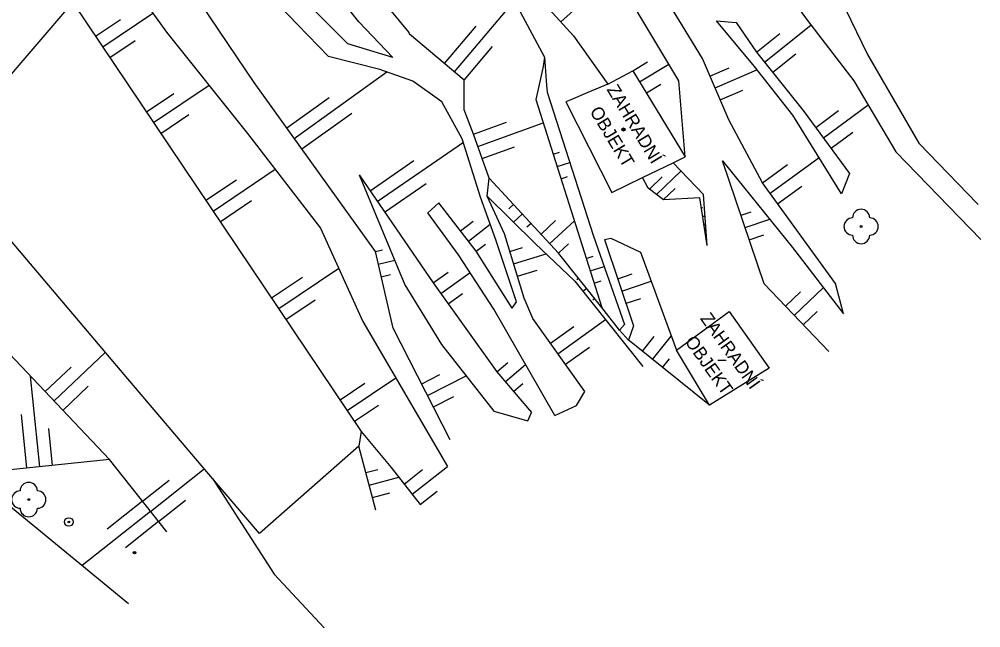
# Model space of a CAD drawing. Extents: x -639440 to -639026, y -1138850 to -1138262.
# Drawn here: x -639133 to -639077.2, y -1138746.6 to -1138711.3 of the extents above; entities that cross this region are included whole.
import ezdxf

# ---------------------------------------------------------------- set-up
doc = ezdxf.new("R2010")
doc.units = 0
for name, color, linetype in [('Vrstva 14', 7, 'Continuous'), ('Vrstva 15', 7, 'Continuous'), ('Vrstva 20', 7, 'Continuous'), ('Vrstva 22', 7, 'Continuous'), ('Vrstva 25', 7, 'Continuous'), ('Vrstva 39', 7, 'Continuous'), ('Vrstva 41', 7, 'Continuous'), ('Vrstva 5', 7, 'Continuous'), ('Vrstva 6', 7, 'Continuous'), ('Vrstva 7', 7, 'Continuous')]:
    doc.layers.add(name, color=color, linetype=linetype)

msp = doc.modelspace()

# ---------------------------------------------------------------- linework, layer by layer
at = {"layer": 'Vrstva 14'}
for p, q in [((-639110.36, -1138712.02), (-639116.41, -1138704.78)), ((-639090.86, -1138706.35), (-639087.24, -1138711.33)), ((-639113.3, -1138711.41), (-639116.94, -1138706.79)), ((-639127.37, -1138707.94), (-639124.46, -1138712)), ((-639093.34, -1138713.54), (-639096.39, -1138708.53)), ((-639103.74, -1138709), (-639100.82, -1138712.23)), ((-639094.71, -1138714.83), (-639098.05, -1138709.26)), ((-639116.85, -1138711.56), (-639118.69, -1138709.65)), ((-639104.71, -1138709.34), (-639102.5, -1138713.46)), ((-639119.36, -1138714.93), (-639122.47, -1138710.35)), ((-639113.92, -1138712.69), (-639116.43, -1138710.19)), ((-639111.32, -1138713.47), (-639113.3, -1138711.41)), ((-639092.51, -1138711.36), (-639091.38, -1138711.44)), ((-639090.32, -1138714.01), (-639092.51, -1138711.36)), ((-639091.38, -1138711.44), (-639090.19, -1138713.16)), ((-639087.24, -1138711.33), (-639084.54, -1138714.83)), ((-639124.46, -1138712), (-639119.75, -1138717.9)), ((-639115.05, -1138713.43), (-639116.85, -1138711.56)), ((-639110.35, -1138712.12), (-639110.36, -1138712.02)), ((-639107.17, -1138714.8), (-639110.35, -1138712.12)), ((-639100.82, -1138712.23), (-639098.83, -1138715.02)), ((-639111.32, -1138713.47), (-639113.92, -1138712.69)), ((-639090.19, -1138713.16), (-639087.48, -1138716.55)), ((-639112.08, -1138714.17), (-639115.05, -1138713.43)), ((-639102.5, -1138713.46), (-639102.59, -1138714.01)), ((-639102.5, -1138713.46), (-639102.4, -1138715.08)), ((-639091.8, -1138717.1), (-639093.34, -1138713.54)), ((-639110.15, -1138714.86), (-639112.08, -1138714.17)), ((-639102.59, -1138714.01), (-639103.01, -1138715.91)), ((-639088.09, -1138716.82), (-639090.32, -1138714.01)), ((-639108.47, -1138716.05), (-639110.15, -1138714.86)), ((-639107.17, -1138716.52), (-639107.17, -1138714.8)), ((-639094.34, -1138719.25), (-639094.71, -1138714.83)), ((-639084.54, -1138714.83), (-639082.11, -1138718.95)), ((-639112.33, -1138724.74), (-639119.36, -1138714.93)), ((-639102.4, -1138715.08), (-639102.35, -1138715.49)), ((-639103.01, -1138715.91), (-639099.17, -1138728)), ((-639102.35, -1138715.49), (-639099.66, -1138723.85)), ((-639107.28, -1138718.2), (-639108.47, -1138716.05)), ((-639106.64, -1138717.93), (-639107.17, -1138716.52)), ((-639087.48, -1138716.55), (-639084.79, -1138720.21)), ((-639089.85, -1138720.75), (-639091.8, -1138717.1)), ((-639085.25, -1138721.39), (-639088.09, -1138716.82)), ((-639119.75, -1138717.9), (-639115.52, -1138723.39)), ((-639106.23, -1138721.58), (-639107.28, -1138718.2)), ((-639105.72, -1138720.48), (-639106.64, -1138717.93)), ((-639082.11, -1138718.95), (-639077.17, -1138724.05)), ((-639093.28, -1138721.44), (-639095.04, -1138719.59)), ((-639089.75, -1138726.62), (-639092.16, -1138719.47)), ((-639092.16, -1138719.47), (-639088.11, -1138724.5)), ((-639113.28, -1138720.28), (-639108.97, -1138726.56)), ((-639113.28, -1138720.28), (-639110.61, -1138726.68)), ((-639096.48, -1138721.06), (-639096.81, -1138720.44)), ((-639084.79, -1138720.21), (-639085.25, -1138721.39)), ((-639105.84, -1138721.53), (-639105.72, -1138720.48)), ((-639101.69, -1138724.83), (-639105.72, -1138720.48)), ((-639085.6, -1138726.6), (-639089.85, -1138720.75)), ((-639105.33, -1138724.06), (-639106.23, -1138721.58)), ((-639105.84, -1138721.53), (-639103.04, -1138724.28)), ((-639104.84, -1138723.72), (-639105.84, -1138721.53)), ((-639095.59, -1138721.75), (-639096.48, -1138721.06)), ((-639093.06, -1138724.39), (-639093.28, -1138721.44)), ((-639109.28, -1138722.5), (-639108.65, -1138721.92)), ((-639106.47, -1138724.73), (-639108.65, -1138721.92)), ((-639093.49, -1138721.62), (-639095.59, -1138721.75)), ((-639093.06, -1138724.39), (-639093.49, -1138721.62)), ((-639107.5, -1138724.93), (-639109.28, -1138722.5)), ((-639115.52, -1138723.39), (-639113.05, -1138728.8)), ((-639103.69, -1138727.44), (-639104.84, -1138723.72)), ((-639104.13, -1138727.67), (-639105.33, -1138724.06)), ((-639103.04, -1138724.28), (-639100.74, -1138726.47)), ((-639099.66, -1138723.85), (-639097.87, -1138728.98)), ((-639099.02, -1138724.05), (-639098.66, -1138723.96)), ((-639099.02, -1138724.05), (-639097.33, -1138729.05)), ((-639098.66, -1138723.96), (-639096.94, -1138724.77)), ((-639111.29, -1138729.19), (-639112.33, -1138724.74)), ((-639105.45, -1138728.08), (-639107.5, -1138724.93)), ((-639104.38, -1138728.03), (-639106.47, -1138724.73)), ((-639099.17, -1138728), (-639101.69, -1138724.83)), ((-639096.94, -1138724.77), (-639094.85, -1138730.47)), ((-639088.11, -1138724.5), (-639085.14, -1138728.35)), ((-639108.97, -1138726.56), (-639105.28, -1138731.73)), ((-639100.74, -1138726.47), (-639096.79, -1138731.41)), ((-639086, -1138730.55), (-639089.75, -1138726.62)), ((-639085.14, -1138728.35), (-639085.6, -1138726.6)), ((-639110.61, -1138726.68), (-639108.48, -1138730.13)), ((-639104.38, -1138728.03), (-639104.13, -1138727.67)), ((-639103.19, -1138728.63), (-639103.69, -1138727.44)), ((-639101.91, -1138734.26), (-639105.45, -1138728.08)), ((-639098.16, -1138729.3), (-639099.17, -1138728)), ((-639113.05, -1138728.8), (-639108.139, -1138737.215)), ((-639100.16, -1138732.87), (-639103.19, -1138728.63)), ((-639107.98, -1138735.67), (-639111.29, -1138729.19)), ((-639097.87, -1138728.98), (-639098.16, -1138729.3)), ((-639097.62, -1138729.89), (-639098.16, -1138729.3)), ((-639097.33, -1138729.05), (-639097.62, -1138729.89)), ((-639134.45, -1138729.77), (-639127.78, -1138736.82)), ((-639097.29, -1138730.16), (-639097.62, -1138729.89)), ((-639108.48, -1138730.13), (-639105.45, -1138734.01)), ((-639092.92, -1138733.66), (-639097.29, -1138730.16)), ((-639105.28, -1138731.73), (-639103.27, -1138734.08)), ((-639100.64, -1138733.68), (-639100.16, -1138732.87)), ((-639101.91, -1138734.26), (-639100.64, -1138733.68)), ((-639105.45, -1138734.01), (-639103.47, -1138734.57)), ((-639103.47, -1138734.57), (-639103.27, -1138734.08)), ((-639112.3, -1138739.75), (-639113.3, -1138736.03)), ((-639127.78, -1138736.82), (-639135.85, -1138737.64)), ((-639124.44, -1138741.02), (-639127.78, -1138736.82)), ((-639135.85, -1138737.64), (-639126.67, -1138745.17)), ((-639121.79, -1138737.92), (-639118.2, -1138743.47)), ((-639118.2, -1138743.47), (-639115.31, -1138746.58))]:
    msp.add_line(p, q, dxfattribs=at)
at = {"layer": 'Vrstva 15'}
for p, q in [((-639107.743, -1138714.317), (-639104.259, -1138710.182)), ((-639101.568, -1138711.403), (-639100.109, -1138710.084)), ((-639128.166, -1138712.866), (-639125.247, -1138710.902)), ((-639128.585, -1138712.244), (-639127.135, -1138711.268)), ((-639108.317, -1138713.833), (-639106.479, -1138711.652)), ((-639090.19, -1138713.16), (-639088.836, -1138712.078)), ((-639089.721, -1138713.746), (-639087.034, -1138711.598)), ((-639127.748, -1138713.488), (-639126.279, -1138712.5)), ((-639107.17, -1138714.8), (-639105.524, -1138712.846)), ((-639097.37, -1138714.25), (-639096.522, -1138713.736)), ((-639089.253, -1138714.332), (-639087.914, -1138713.262)), ((-639117.038, -1138718.171), (-639111.663, -1138714.319)), ((-639096.981, -1138714.891), (-639095.288, -1138713.865)), ((-639092.899, -1138714.559), (-639091.782, -1138714.075)), ((-639092.602, -1138715.247), (-639090.172, -1138714.196)), ((-639125.209, -1138717.261), (-639121.99, -1138715.094)), ((-639096.593, -1138715.533), (-639095.748, -1138715.021)), ((-639092.304, -1138715.935), (-639090.997, -1138715.37)), ((-639125.628, -1138716.638), (-639124.044, -1138715.572)), ((-639117.474, -1138717.561), (-639115.023, -1138715.804)), ((-639086.755, -1138717.536), (-639085.426, -1138716.559)), ((-639086.311, -1138718.14), (-639083.714, -1138716.231)), ((-639124.79, -1138717.883), (-639123.155, -1138716.783)), ((-639116.601, -1138718.78), (-639113.702, -1138716.703)), ((-639106.64, -1138717.931), (-639104.724, -1138717.239)), ((-639106.385, -1138718.636), (-639102.58, -1138717.263)), ((-639085.867, -1138718.744), (-639084.599, -1138717.812)), ((-639112.217, -1138721.829), (-639107.218, -1138718.398)), ((-639106.131, -1138719.342), (-639104.242, -1138718.66)), ((-639102.002, -1138719.084), (-639101.635, -1138718.967)), ((-639089.409, -1138721.357), (-639086.558, -1138719.285)), ((-639112.641, -1138721.211), (-639110.095, -1138719.463)), ((-639101.775, -1138719.799), (-639101.039, -1138719.565)), ((-639089.85, -1138720.75), (-639088.402, -1138719.698)), ((-639121.756, -1138722.391), (-639118.156, -1138719.968)), ((-639101.548, -1138720.513), (-639101.179, -1138720.396)), ((-639096.411, -1138721.114), (-639095.669, -1138720.41)), ((-639096.011, -1138721.424), (-639094.583, -1138720.068)), ((-639122.175, -1138721.769), (-639120.395, -1138720.571)), ((-639111.793, -1138722.447), (-639109.389, -1138720.798)), ((-639088.968, -1138721.964), (-639087.565, -1138720.944)), ((-639095.611, -1138721.734), (-639094.925, -1138721.082)), ((-639121.338, -1138723.013), (-639119.518, -1138721.788)), ((-639104.302, -1138722.011), (-639104.572, -1138722.261)), ((-639103.792, -1138722.561), (-639104.306, -1138723.037)), ((-639093.4, -1138722.201), (-639093.312, -1138722.195)), ((-639093.323, -1138722.697), (-639093.187, -1138722.687)), ((-639091.094, -1138722.633), (-639090.511, -1138722.437)), ((-639107.389, -1138723.545), (-639106.659, -1138722.978)), ((-639106.93, -1138724.137), (-639105.66, -1138723.152)), ((-639103.282, -1138723.111), (-639103.526, -1138723.337)), ((-639102.709, -1138723.73), (-639101.866, -1138722.948)), ((-639102.2, -1138724.28), (-639100.772, -1138722.957)), ((-639093.246, -1138723.193), (-639093.198, -1138723.189)), ((-639090.854, -1138723.344), (-639089.428, -1138722.863)), ((-639090.615, -1138724.055), (-639089.771, -1138723.77)), ((-639106.47, -1138724.73), (-639105.93, -1138724.311)), ((-639101.69, -1138724.83), (-639101.105, -1138724.288)), ((-639112.33, -1138724.74), (-639111.915, -1138724.643)), ((-639104.525, -1138724.738), (-639103.783, -1138724.509)), ((-639104.304, -1138725.455), (-639102.418, -1138724.872)), ((-639112.159, -1138725.47), (-639111.207, -1138725.248)), ((-639100.078, -1138725.142), (-639099.687, -1138725.017)), ((-639117.943, -1138728.057), (-639114.459, -1138725.713)), ((-639108.97, -1138726.56), (-639108.106, -1138725.943)), ((-639108.534, -1138727.17), (-639106.832, -1138725.956)), ((-639104.082, -1138726.171), (-639102.939, -1138725.818)), ((-639099.851, -1138725.856), (-639099.049, -1138725.602)), ((-639098.25, -1138726.327), (-639097.413, -1138726.045)), ((-639118.362, -1138727.435), (-639116.569, -1138726.228)), ((-639111.989, -1138726.201), (-639111.452, -1138726.075)), ((-639100.523, -1138726.297), (-639100.632, -1138726.384)), ((-639099.624, -1138726.571), (-639099.213, -1138726.441)), ((-639098.01, -1138727.038), (-639096.318, -1138726.466)), ((-639100.057, -1138726.885), (-639100.272, -1138727.056)), ((-639088.519, -1138727.91), (-639087.644, -1138727.075)), ((-639088.001, -1138728.453), (-639086.308, -1138726.836)), ((-639117.524, -1138728.68), (-639115.834, -1138727.542)), ((-639108.099, -1138727.781), (-639107.261, -1138727.183)), ((-639099.59, -1138727.472), (-639099.697, -1138727.556)), ((-639097.77, -1138727.748), (-639096.915, -1138727.459)), ((-639087.484, -1138728.995), (-639086.665, -1138728.214)), ((-639101.729, -1138730.675), (-639098.96, -1138728.696)), ((-639102.165, -1138730.065), (-639100.797, -1138729.087)), ((-639096.823, -1138730.534), (-639096.139, -1138729.679)), ((-639096.238, -1138731.003), (-639095.152, -1138729.647)), ((-639101.293, -1138731.285), (-639099.892, -1138730.284)), ((-639130.998, -1138733.419), (-639128.006, -1138730.588)), ((-639095.653, -1138731.471), (-639095.251, -1138730.971)), ((-639131.513, -1138732.874), (-639130.003, -1138731.445)), ((-639105.28, -1138731.73), (-639104.635, -1138731.179)), ((-639104.793, -1138732.3), (-639103.611, -1138731.29)), ((-639131.825, -1138737.231), (-639132.359, -1138731.98)), ((-639113.961, -1138733.975), (-639111.138, -1138732.076)), ((-639109.638, -1138732.424), (-639108.584, -1138731.886)), ((-639109.297, -1138733.092), (-639107.059, -1138731.949)), ((-639130.482, -1138733.964), (-639129.001, -1138732.562)), ((-639114.38, -1138733.353), (-639112.948, -1138732.39)), ((-639104.305, -1138732.87), (-639103.768, -1138732.411)), ((-639108.955, -1138733.76), (-639107.772, -1138733.156)), ((-639113.542, -1138734.597), (-639112.151, -1138733.661)), ((-639132.571, -1138737.307), (-639132.887, -1138734.197)), ((-639131.079, -1138737.155), (-639131.297, -1138735.014)), ((-639110.193, -1138738.83), (-639108.139, -1138737.215)), ((-639125.39, -1138739.825), (-639122.275, -1138737.348)), ((-639112.884, -1138737.576), (-639112.182, -1138737.387)), ((-639110.657, -1138738.241), (-639109.589, -1138737.401)), ((-639125.857, -1138739.238), (-639124.309, -1138738.006)), ((-639112.69, -1138738.3), (-639110.973, -1138737.839)), ((-639112.495, -1138739.025), (-639111.482, -1138738.752)), ((-639109.73, -1138739.42), (-639108.743, -1138738.645)), ((-639125.858, -1138739.237), (-639127.9, -1138740.861)), ((-639124.924, -1138740.412), (-639123.357, -1138739.166)), ((-639125.391, -1138739.824), (-639129.35, -1138742.972)), ((-639124.924, -1138740.411), (-639126.84, -1138741.935))]:
    msp.add_line(p, q, dxfattribs=at)
at = {"layer": 'Vrstva 20'}
for radius in [0.075, 0.0204]:
    msp.add_circle((-639126.32, -1138742.22), radius, dxfattribs=at)
at = {"layer": 'Vrstva 22'}
for centre in [(-639084.12, -1138723.29), (-639132.46, -1138739.14)]:
    msp.add_circle(centre, 0.05, dxfattribs=at)
for centre, start, end in [((-639084.12, -1138722.79), 0, 180), ((-639084.62, -1138723.29), 90, 270), ((-639083.62, -1138723.29), 270, 90), ((-639084.12, -1138723.79), 180, 0), ((-639132.46, -1138738.64), 0, 180), ((-639132.96, -1138739.14), 90, 270), ((-639131.96, -1138739.14), 270, 90), ((-639132.46, -1138739.64), 180, 0)]:
    msp.add_arc(centre, 0.5, start, end, dxfattribs=at)
at = {"layer": 'Vrstva 25'}
for radius in [0.25, 0.05]:
    msp.add_circle((-639130.13, -1138740.44), radius, dxfattribs=at)
at = {"layer": 'Vrstva 39'}
msp.add_line((-639092.45, -1138731.05), (-639091.95, -1138731.05), dxfattribs=at)
for radius in [0.09, 0.0398]:
    msp.add_circle((-639097.92, -1138717.66), radius, dxfattribs=at)
at = {"layer": 'Vrstva 5'}
for p, q in [((-639098.83, -1138715.02), (-639097.37, -1138714.25)), ((-639097.37, -1138714.25), (-639094.34, -1138719.25)), ((-639098.83, -1138715.02), (-639100, -1138715.52)), ((-639100.98, -1138715.93), (-639101.26, -1138716.05)), ((-639100, -1138715.52), (-639100.98, -1138715.93)), ((-639101.26, -1138716.05), (-639098.59, -1138721.31)), ((-639095.04, -1138719.59), (-639094.34, -1138719.25)), ((-639096.81, -1138720.44), (-639095.04, -1138719.59)), ((-639098.59, -1138721.31), (-639096.81, -1138720.44)), ((-639094.85, -1138730.47), (-639091.79, -1138728.23)), ((-639091.79, -1138728.23), (-639089.45, -1138731.52)), ((-639092.92, -1138733.66), (-639094.85, -1138730.47)), ((-639089.45, -1138731.52), (-639092.92, -1138733.66))]:
    msp.add_line(p, q, dxfattribs=at)
at = {"layer": 'Vrstva 6'}
msp.add_line((-639100, -1138715.52), (-639100.98, -1138715.93), dxfattribs=at)
at = {"layer": 'Vrstva 7'}
for p, q in [((-639137.55, -1138719.19), (-639129.9, -1138710.29)), ((-639129.9, -1138710.29), (-639113.15, -1138735.18)), ((-639085.05, -1138710.64), (-639083.74, -1138713.3)), ((-639083.74, -1138713.3), (-639080.76, -1138718.46)), ((-639080.76, -1138718.46), (-639077.36, -1138721.98)), ((-639077.36, -1138721.98), (-639077.32, -1138722.02)), ((-639126.91, -1138731.88), (-639134.58, -1138722.84)), ((-639121.79, -1138737.92), (-639126.91, -1138731.88)), ((-639113.15, -1138735.18), (-639113.3, -1138736.03)), ((-639113.15, -1138735.18), (-639111.42, -1138737.27)), ((-639113.3, -1138736.03), (-639119.06, -1138741.11)), ((-639111.42, -1138737.27), (-639109.73, -1138739.42)), ((-639119.06, -1138741.11), (-639121.79, -1138737.92))]:
    msp.add_line(p, q, dxfattribs=at)

# ---------------------------------------------------------------- texts
at = {"layer": 'Vrstva 41'}
for s, rotation, p in [('ZAHRADNÍ', 301.2159, (-639098.919, -1138715.335)), ('OBJEKT', 301.2159, (-639099.906, -1138716.6)), ('ZAHRADNÍ', 305.4222, (-639093.496, -1138728.629)), ('OBJEKT', 305.4222, (-639094.388, -1138729.963))]:
    msp.add_text(s, height=0.75, rotation=rotation, dxfattribs=at).set_placement(p)

doc.saveas('drawing.dxf')
